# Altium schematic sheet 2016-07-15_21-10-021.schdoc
size 383 x 148 mm; SheetNumber: 1; SheetTotal: 1
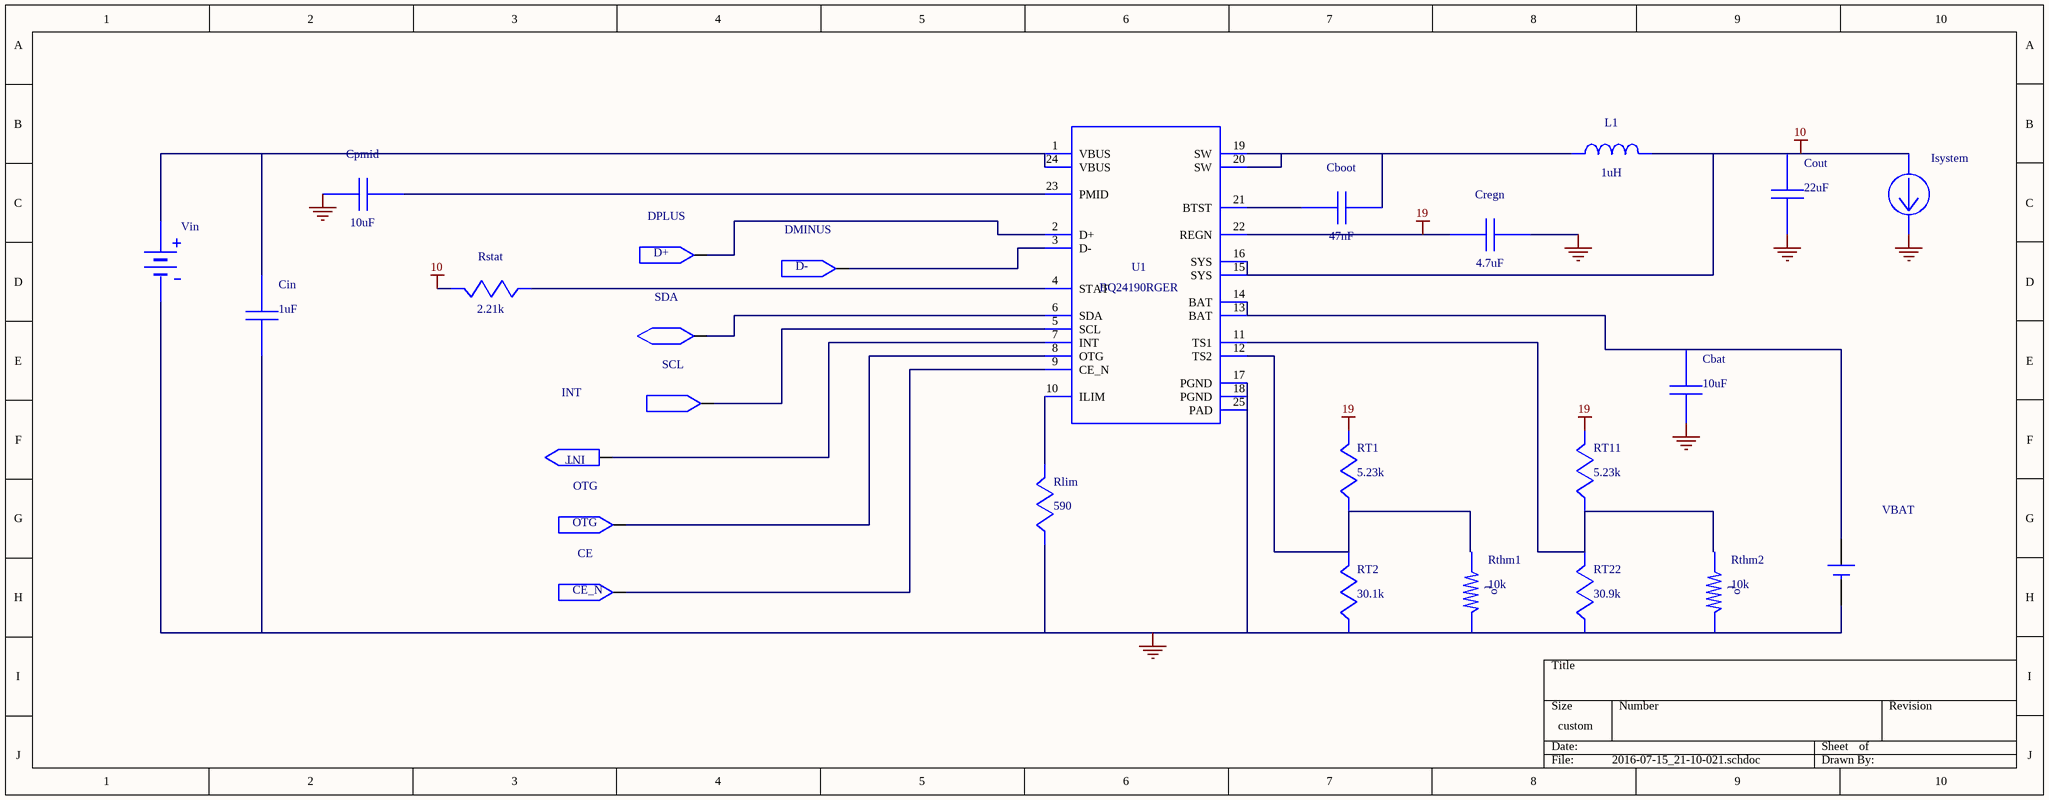
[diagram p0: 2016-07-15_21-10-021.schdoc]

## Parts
Cbat  value 10uF  (hidden comment: GRM219R60J106KE19D)
Cboot  value 47nF  (hidden comment: GRM155R61A473KA01D)
CE  WB_CE_N  (value not drawn)
Cin  value 1uF  (hidden comment: GRM188R61A105KA61D)
Cout  value 22uF  (hidden comment: LMK212BJ226MG-T)
Cpmid  value 10uF  (hidden comment: GRM21BR61A106KE19L)
Cregn  value 4.7uF  (hidden comment: GRM21BR61E475KA12L)
DMINUS  WB_DMINUS  (value not drawn)
DPLUS  WB_DPLUS  (value not drawn)
INT  WB_INT_R180  (value not drawn)
Isystem  WB_CURRENT_LOAD  (value not drawn)
L1  value 1uH  (hidden comment: 'VLF252012MT-1R0N')
OTG  WB_OTG  (value not drawn)
Rlim  value 590  (hidden comment: CRCW0402590RFKED)
Rstat  value 2.21k  (hidden comment: CRCW04022K21FKED)
RT1  value 5.23k  (hidden comment: CRCW04025K23FKED)
RT2  value 30.1k  (hidden comment: CRCW040230K1FKED)
RT11  value 5.23k  (hidden comment: CRCW04025K23FKED)
RT22  value 30.9k  (hidden comment: CRCW040230K9FKED)
Rthm1  value 10k  (hidden comment: NCP15XH103E03RC)
Rthm2  value 10k  (hidden comment: NCP15XH103E03RC)
SCL  WB_I2C_SCL  (value not drawn)
SDA  WB_I2C_SDA  (value not drawn)
U1  BQ24190RGER
VBAT  WB_BATTERY_SINGLE_USFP  (value not drawn)
Vin  WB_BATTERY  (value not drawn)

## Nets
0: Cin.2 Cout.2 Cpmid.2 Cregn.2 Isystem.2(-) Rlim.2 RT2.2 RT22.2 Rthm1.2 Rthm2.2 U1.17(PGND) U1.18(PGND) U1.25(PAD) VBAT.2(-) Vin.2(-)
10: Cout.1 Isystem.1(+) L1.2 Rstat.1 U1.15(SYS) U1.16(SYS)
19: Cregn.1 RT1.1 RT11.1 U1.22(REGN)
NetCbat_1: Cbat.1 U1.13(BAT) U1.14(BAT) VBAT.1(+)
NetCboot_1: Cboot.1 L1.1 U1.19(SW) U1.20(SW)
NetCboot_2: Cboot.2 U1.21(BTST)
NetCE_1: CE.1 U1.9(CE_N)
NetCin_1: Cin.1 U1.1(VBUS) U1.24(VBUS) Vin.1(+)
NetCpmid_1: Cpmid.1 U1.23(PMID)
NetDMINUS_1: DMINUS.1 U1.3(D-)
NetDPLUS_1: DPLUS.1 U1.2(D+)
NetINT_1: INT.1 U1.7(INT)
NetOTG_1: OTG.1 U1.8(OTG)
NetRlim_1: Rlim.1 U1.10(ILIM)
NetRstat_2: Rstat.2 U1.4(STAT)
NetRT1_2: RT1.2 RT2.1 U1.12(TS2)
NetRT11_2: RT11.2 RT22.1 U1.11(TS1)
NetSCL_1: SCL.1 U1.5(SCL)
NetSDA_1: SDA.1 U1.6(SDA)

Not connected (* = marked no-connect by the designer): Cbat 2; Rthm1 1; Rthm2 1

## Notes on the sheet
- (near DPLUS) D+
- (near DMINUS) D-
- (near INT) INT
- (near OTG) OTG
- (near CE) CE_N
- (near Rthm1) t
- (near Rthm1) o
- (near Rthm2) t
- (near Rthm2) o
- Labels drawn without touching a wire or pin: 0

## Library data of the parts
Cbat = GRM219R60J106KE19D: GRM219R60J106KE1; Manufacturer Name: MuRata
Cboot = GRM155R61A473KA01D: GRM155R61A473KA0; Manufacturer Name: MuRata
Cin = GRM188R61A105KA61D: GRM188R61A105KA6; Manufacturer Name: MuRata
Cout = LMK212BJ226MG-T: Manufacturer Name: Taiyo Yuden
Cpmid = GRM21BR61A106KE19L: GRM21BR61A106KE1; Manufacturer Name: MuRata
Cregn = GRM21BR61E475KA12L: GRM21BR61E475KA1; Manufacturer Name: MuRata
L1 = 'VLF252012MT-1R0N': VLF252012MT-1R0N; Manufacturer Name: TDK
Rlim = CRCW0402590RFKED: Manufacturer Name: Vishay-Dale
Rstat = CRCW04022K21FKED: Manufacturer Name: Vishay-Dale
RT1 RT11 = CRCW04025K23FKED: Manufacturer Name: Vishay-Dale
RT2 = CRCW040230K1FKED: Manufacturer Name: Vishay-Dale
RT22 = CRCW040230K9FKED: Manufacturer Name: Vishay-Dale
Rthm1 Rthm2 = NCP15XH103E03RC: Manufacturer Name: MuRata
U1 = BQ24190RGER: Manufacturer Name: Texas Instruments
VBAT = WB_BATTERY_SINGLE_USFP: WB_BATTERY_SINGL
